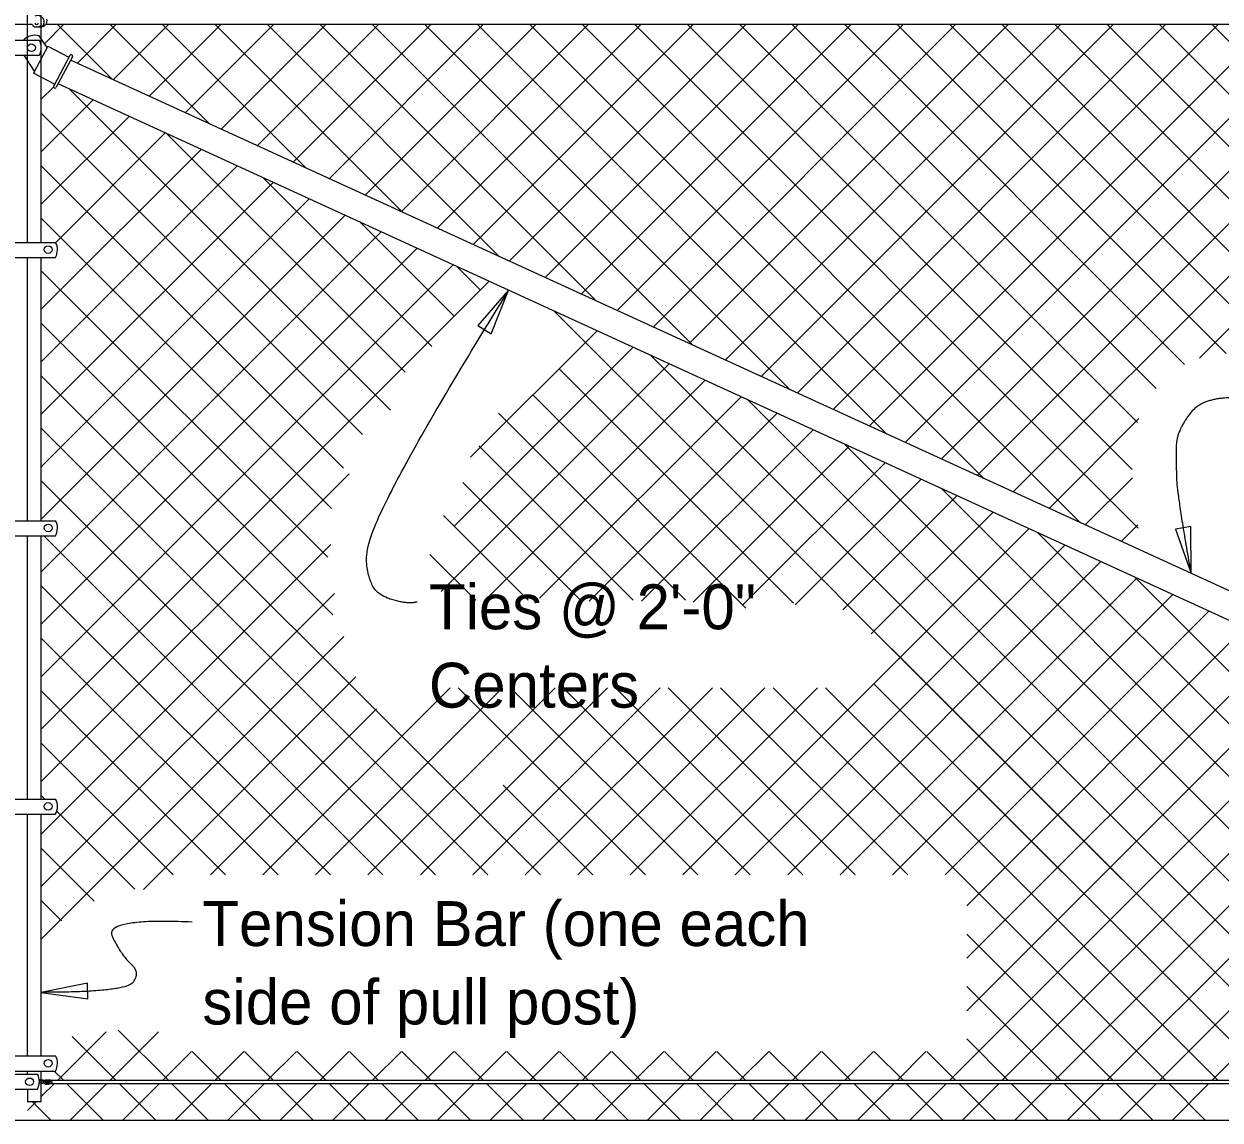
# Model space of a CAD drawing. Extents: x 0 to 41.2, y 0 to 26.
# Drawn here: x 12.4 to 17.77, y 17.47 to 22.39 of the extents above; entities that cross this region are included whole.
import ezdxf

# ---------------------------------------------------------------- set-up
doc = ezdxf.new("R2010")
doc.units = 0
for name, color, linetype in [('Dimension', 7, 'Continuous'), ('Miscellaneous', 7, 'Continuous'), ('SteelMisc', 7, 'Continuous'), ('SupstrConc', 7, 'Continuous'), ('TextStructures', 7, 'Continuous')]:
    doc.layers.add(name, color=color, linetype=linetype)

msp = doc.modelspace()

# ---------------------------------------------------------------- linework, layer by layer
at = {"layer": 'Dimension'}
for points in [[(14.5761, 21.1957), (14.4371, 21.0368), (14.4972, 20.9998)], [(17.6408, 19.9239), (17.6405, 20.1351), (17.5709, 20.1232)], [(12.4771, 18.0429), (12.6863, 18.0139), (12.6842, 18.0844)]]:
    msp.add_lwpolyline(points, close=True, dxfattribs=at)
for points in [[(14.1644, 19.7962), (14.1177, 19.782), (13.9347, 19.8493), (13.9433, 20.1759), (14.5761, 21.1958)], [(17.8509, 20.7118), (17.6943, 20.72), (17.5763, 20.5615), (17.5733, 20.4403), (17.578, 20.2726), (17.6407, 19.9238)], [(13.1545, 18.3586), (12.7557, 18.3765), (12.8361, 18.2097), (12.9224, 18.1322), (12.8539, 18.0428), (12.4771, 18.0428)]]:
    msp.add_open_spline(points, degree=2, dxfattribs=at)
at = {"layer": 'Miscellaneous'}
for p, q in [((12.4911, 22.303), (12.5782, 22.39)), ((12.5487, 22.39), (12.7955, 22.1432)), ((12.6389, 22.215), (12.8139, 22.39)), ((12.7844, 22.39), (13.2304, 21.944)), ((12.8005, 22.1409), (13.0496, 22.39)), ((12.9622, 22.0669), (13.2853, 22.39)), ((13.0201, 22.39), (13.6653, 21.7448)), ((13.1238, 21.9928), (13.521, 22.39)), ((13.2558, 22.39), (14.1002, 21.5456)), ((13.2855, 21.9188), (13.7567, 22.39)), ((13.4471, 21.8448), (13.9924, 22.39)), ((13.4916, 22.39), (14.5351, 21.3464)), ((13.6088, 21.7707), (14.2281, 22.39)), ((13.7273, 22.39), (14.9701, 21.1472)), ((13.7705, 21.6967), (14.4638, 22.39)), ((13.9321, 21.6226), (14.6995, 22.39)), ((13.963, 22.39), (15.405, 20.948)), ((14.0938, 21.5486), (14.9352, 22.39)), ((14.1987, 22.39), (15.8399, 20.7488)), ((14.2554, 21.4745), (15.1709, 22.39)), ((14.4171, 21.4005), (15.4066, 22.39)), ((14.4344, 22.39), (16.2748, 20.5496)), ((14.5787, 21.3264), (15.6423, 22.39)), ((14.6701, 22.39), (16.7097, 20.3504)), ((14.7404, 21.2524), (15.878, 22.39)), ((14.9021, 21.1784), (16.1137, 22.39)), ((14.9058, 22.39), (17.1446, 20.1512)), ((15.0637, 21.1043), (16.3494, 22.39)), ((15.1415, 22.39), (17.4036, 20.1279)), ((15.2254, 21.0303), (16.5851, 22.39)), ((15.3772, 22.39), (17.3758, 20.3914)), ((15.387, 20.9562), (16.8208, 22.39)), ((15.5487, 20.8822), (17.0565, 22.39)), ((15.6129, 22.39), (16.224, 21.7789)), ((15.7103, 20.8081), (17.2922, 22.39)), ((15.8486, 22.39), (16.224, 22.0146)), ((15.872, 20.7341), (17.5279, 22.39)), ((16.0337, 20.66), (17.7636, 22.39)), ((16.0843, 22.39), (17.6113, 20.8629)), ((16.1953, 20.586), (17.9993, 22.39)), ((16.32, 22.39), (17.7983, 20.9117)), ((16.357, 20.5119), (18.235, 22.39)), ((16.5186, 20.4379), (18.4707, 22.39)), ((16.5557, 22.39), (17.9778, 20.9679)), ((16.6803, 20.3639), (18.7064, 22.39)), ((16.7914, 22.39), (18.2135, 20.9679)), ((16.8419, 20.2898), (18.9421, 22.39)), ((17.0271, 22.39), (18.4492, 20.9679)), ((17.2628, 22.39), (18.6849, 20.9679)), ((17.4985, 22.39), (18.9206, 20.9679)), ((17.679, 20.8912), (19.1778, 22.39)), ((17.7342, 22.39), (19.1563, 20.9679)), ((12.4771, 22.0532), (12.532, 22.1081)), ((12.6041, 22.099), (14.0454, 20.6576)), ((12.4771, 21.8175), (12.71, 22.0505)), ((15.95, 22.0528), (17.4005, 20.6024)), ((16.1857, 22.0528), (17.4843, 20.7543)), ((12.4771, 21.9903), (13.9198, 20.5475)), ((12.4771, 21.5818), (12.8717, 21.9764)), ((12.5416, 21.4106), (13.0333, 21.9024)), ((13.0389, 21.8998), (14.1107, 20.8281)), ((12.4771, 21.1104), (13.195, 21.8283)), ((12.4771, 21.7546), (13.8345, 20.3972)), ((12.4771, 20.8747), (13.3567, 21.7543)), ((12.4771, 20.639), (13.5183, 21.6802)), ((13.4738, 21.7006), (14.2316, 20.9428)), ((12.4771, 20.4033), (13.68, 21.6062)), ((14.5173, 21.6), (14.649, 21.4683)), ((12.4771, 20.1676), (13.8416, 21.5322)), ((12.4771, 21.5189), (13.78, 20.2159)), ((13.9087, 21.5014), (14.3312, 21.0789)), ((12.4771, 19.9319), (14.0033, 21.4581)), ((12.4771, 19.6962), (14.165, 21.3841)), ((12.4771, 19.4605), (14.3266, 21.31)), ((12.4771, 21.2832), (13.7633, 19.997)), ((14.3436, 21.3022), (14.4491, 21.1968)), ((12.4771, 19.2248), (14.4883, 21.236)), ((14.7785, 21.103), (17.3305, 18.5511)), ((12.4771, 21.0475), (13.7861, 19.7384)), ((14.4052, 20.4458), (14.9733, 21.0138)), ((14.3305, 20.1354), (15.1349, 20.9398)), ((15.2134, 20.9039), (18.4687, 17.6486)), ((14.2734, 19.8426), (15.2966, 20.8658)), ((12.4771, 20.8118), (14.7187, 18.5701)), ((14.4778, 19.8113), (15.4582, 20.7917)), ((14.8026, 20.8432), (15.8555, 19.7904)), ((14.6848, 20.7254), (15.6418, 19.7684)), ((14.7149, 19.8127), (15.6199, 20.7177)), ((15.6483, 20.7047), (18.7044, 17.6486)), ((14.53, 20.6445), (15.3708, 19.8037)), ((14.9378, 19.7999), (15.7815, 20.6436)), ((17.0036, 20.2158), (17.4071, 20.6192)), ((12.4771, 20.5761), (14.483, 18.5701)), ((15.1731, 19.7995), (15.9432, 20.5696)), ((14.4418, 20.497), (15.1351, 19.8037)), ((15.4049, 19.7956), (16.1049, 20.4955)), ((16.0832, 20.5055), (18.9401, 17.6486)), ((15.6276, 19.7826), (16.2665, 20.4215)), ((12.4771, 18.9891), (13.8596, 20.3716)), ((12.4771, 20.3404), (14.2473, 18.5701)), ((14.3708, 20.3323), (14.8994, 19.8037)), ((15.8633, 19.7826), (16.4282, 20.3475)), ((17.1653, 20.1417), (17.3773, 20.3538)), ((16.0774, 19.761), (16.5898, 20.2734)), ((16.5181, 20.3063), (19.1758, 17.6486)), ((14.283, 20.1844), (14.6637, 19.8037)), ((16.2045, 19.6524), (16.7515, 20.1994)), ((12.4884, 20.0933), (14.0116, 18.5701)), ((16.1384, 19.3505), (16.9132, 20.1253)), ((16.953, 20.1071), (19.4115, 17.6486)), ((17.3269, 20.0677), (17.4014, 20.1422)), ((12.4771, 18.7534), (13.778, 20.0543)), ((15.5936, 18.5701), (17.0748, 20.0513)), ((14.2226, 20.0091), (14.428, 19.8037)), ((15.8293, 18.5701), (17.2365, 19.9772)), ((16.065, 18.5701), (17.3981, 19.9032)), ((17.3879, 19.9079), (19.6472, 17.6486)), ((12.4771, 19.869), (13.7759, 18.5701)), ((12.4771, 18.5177), (13.7936, 19.8342)), ((16.3007, 18.5701), (17.5598, 19.8292)), ((16.5364, 18.5701), (17.7215, 19.7551)), ((16.6339, 18.4318), (17.8831, 19.6811)), ((12.4771, 18.282), (13.8357, 19.6406)), ((12.4771, 19.6333), (13.5402, 18.5701)), ((16.2952, 19.5864), (18.233, 17.6486)), ((16.6339, 18.1961), (18.0448, 19.607)), ((16.6339, 17.9604), (18.2064, 19.533)), ((12.9361, 18.5053), (13.8901, 19.4593)), ((16.5577, 17.6486), (18.3681, 19.4589)), ((12.4771, 19.3976), (13.3045, 18.5701)), ((13.4723, 18.5701), (14.3131, 19.4109)), ((13.708, 18.5701), (14.5488, 19.4109)), ((13.9437, 18.5701), (14.7845, 19.4109)), ((14.1794, 18.5701), (15.0202, 19.4109)), ((14.3493, 19.4109), (15.1901, 18.5701)), ((14.4151, 18.5701), (15.2559, 19.4109)), ((14.585, 19.4109), (15.4258, 18.5701)), ((14.6508, 18.5701), (15.4916, 19.4109)), ((14.8207, 19.4109), (15.6615, 18.5701)), ((14.8865, 18.5701), (15.7274, 19.4109)), ((15.0564, 19.4109), (15.8972, 18.5701)), ((15.1222, 18.5701), (15.9631, 19.4109)), ((15.2921, 19.4109), (16.1329, 18.5701)), ((15.3579, 18.5701), (16.1988, 19.4109)), ((15.5278, 19.4109), (16.3686, 18.5701)), ((15.7635, 19.4109), (17.5259, 17.6486)), ((15.9992, 19.4109), (17.7616, 17.6486)), ((16.0143, 19.3958), (16.8591, 18.5511)), ((16.2168, 19.429), (17.0948, 18.5511)), ((16.2349, 19.4109), (17.9973, 17.6486)), ((16.7934, 17.6486), (18.5298, 19.3849)), ((13.2366, 18.5701), (13.9832, 19.3167)), ((17.0291, 17.6486), (18.6914, 19.3109)), ((17.2648, 17.6486), (18.8531, 19.2368)), ((12.4771, 19.1619), (13.0688, 18.5701)), ((17.5005, 17.6486), (19.0147, 19.1628)), ((17.7362, 17.6486), (19.1764, 19.0887)), ((14.5513, 18.9732), (14.9544, 18.5701)), ((12.4771, 18.9262), (12.4923, 18.9109)), ((12.5465, 18.8568), (12.897, 18.5062)), ((12.4771, 18.6905), (12.715, 18.4525)), ((12.4771, 18.4548), (12.5674, 18.3644)), ((16.6339, 18.3049), (17.2902, 17.6486)), ((16.6339, 18.0692), (17.0545, 17.6486)), ((12.5508, 17.6486), (12.7683, 17.8661)), ((12.6161, 17.8443), (12.8118, 17.6486)), ((12.7865, 17.6486), (13.0028, 17.8649)), ((12.8223, 17.8738), (13.0476, 17.6486)), ((16.6339, 17.8335), (16.8188, 17.6486)), ((13.0222, 17.6486), (13.1513, 17.7777)), ((13.1541, 17.7777), (13.2833, 17.6486)), ((13.2579, 17.6486), (13.387, 17.7777)), ((13.3898, 17.7777), (13.519, 17.6486)), ((13.4936, 17.6486), (13.6227, 17.7777)), ((13.6255, 17.7777), (13.7547, 17.6486)), ((13.7293, 17.6486), (13.8584, 17.7777)), ((13.8612, 17.7777), (13.9904, 17.6486)), ((13.965, 17.6486), (14.0941, 17.7777)), ((14.0969, 17.7777), (14.2261, 17.6486)), ((14.2007, 17.6486), (14.3298, 17.7777)), ((14.3326, 17.7777), (14.4618, 17.6486)), ((14.4364, 17.6486), (14.5655, 17.7777)), ((14.5683, 17.7777), (14.6975, 17.6486)), ((14.6721, 17.6486), (14.8012, 17.7777)), ((14.804, 17.7777), (14.9332, 17.6486)), ((14.9078, 17.6486), (15.0369, 17.7777)), ((15.0397, 17.7777), (15.1689, 17.6486)), ((15.1435, 17.6486), (15.2726, 17.7777)), ((15.2754, 17.7777), (15.4046, 17.6486)), ((15.3792, 17.6486), (15.5083, 17.7777)), ((15.5111, 17.7777), (15.6403, 17.6486)), ((15.6149, 17.6486), (15.744, 17.7777)), ((15.7468, 17.7777), (15.876, 17.6486)), ((15.8506, 17.6486), (15.9797, 17.7777)), ((15.9825, 17.7777), (16.1117, 17.6486)), ((16.0863, 17.6486), (16.2155, 17.7777)), ((16.2182, 17.7777), (16.3474, 17.6486)), ((16.322, 17.6486), (16.4503, 17.7768)), ((16.4539, 17.7777), (16.5831, 17.6486)), ((12.5351, 17.6896), (12.5761, 17.6486)), ((12.4771, 17.5748), (12.536, 17.6338)), ((12.5909, 17.6338), (12.7554, 17.4693)), ((12.6072, 17.4693), (12.7717, 17.6338)), ((12.8266, 17.6338), (12.9911, 17.4693)), ((12.8429, 17.4693), (13.0074, 17.6338)), ((13.0623, 17.6338), (13.2268, 17.4693)), ((13.0786, 17.4693), (13.2431, 17.6338)), ((13.298, 17.6338), (13.4625, 17.4693)), ((13.3143, 17.4693), (13.4788, 17.6338)), ((13.5337, 17.6338), (13.6982, 17.4693)), ((13.5501, 17.4693), (13.7145, 17.6338)), ((13.7694, 17.6338), (13.9339, 17.4693)), ((13.7858, 17.4693), (13.9502, 17.6338)), ((14.0051, 17.6338), (14.1696, 17.4693)), ((14.0215, 17.4693), (14.1859, 17.6338)), ((14.2408, 17.6338), (14.4053, 17.4693)), ((14.2572, 17.4693), (14.4216, 17.6338)), ((14.4765, 17.6338), (14.641, 17.4693)), ((14.4929, 17.4693), (14.6573, 17.6338)), ((14.7122, 17.6338), (14.8767, 17.4693)), ((14.7286, 17.4693), (14.893, 17.6338)), ((14.9479, 17.6338), (15.1124, 17.4693)), ((14.9643, 17.4693), (15.1287, 17.6338)), ((15.1836, 17.6338), (15.3481, 17.4693)), ((15.2, 17.4693), (15.3644, 17.6338)), ((15.4193, 17.6338), (15.5838, 17.4693)), ((15.4357, 17.4693), (15.6001, 17.6338)), ((15.655, 17.6338), (15.8195, 17.4693)), ((15.6714, 17.4693), (15.8359, 17.6338)), ((15.8907, 17.6338), (16.0552, 17.4693)), ((15.9071, 17.4693), (16.0716, 17.6338)), ((16.1264, 17.6338), (16.2909, 17.4693)), ((16.1428, 17.4693), (16.3073, 17.6338)), ((16.3621, 17.6338), (16.5266, 17.4693)), ((16.3785, 17.4693), (16.543, 17.6338)), ((16.5978, 17.6338), (16.7623, 17.4693)), ((16.6142, 17.4693), (16.7787, 17.6338)), ((16.8335, 17.6338), (16.998, 17.4693)), ((16.8499, 17.4693), (17.0144, 17.6338)), ((17.0692, 17.6338), (17.2337, 17.4693)), ((17.0856, 17.4693), (17.2501, 17.6338)), ((17.3049, 17.6338), (17.4694, 17.4693)), ((17.3213, 17.4693), (17.4858, 17.6338)), ((17.5406, 17.6338), (17.7051, 17.4693)), ((17.557, 17.4693), (17.7215, 17.6338)), ((12.4146, 17.5123), (12.455, 17.5528)), ((12.4362, 17.5528), (12.5197, 17.4693))]:
    msp.add_line(p, q, dxfattribs=at)
at = {"layer": 'SteelMisc'}
for p, q in [((12.4146, 21.4109), (12.4146, 22.5933)), ((12.4771, 21.4109), (12.4771, 22.5933)), ((12.352, 22.39), (12.4351, 22.39)), ((12.4978, 22.39), (21.9118, 22.39)), ((11.9439, 22.3192), (12.4686, 22.3192)), ((12.5028, 22.2852), (12.468, 22.3383)), ((11.9439, 22.2514), (12.4686, 22.2514)), ((12.4467, 22.1792), (12.3998, 22.2509)), ((12.5062, 22.2918), (12.4425, 22.1712)), ((12.5062, 22.2918), (12.6005, 22.2419)), ((12.6051, 22.2506), (12.5327, 22.1134)), ((12.617, 22.2443), (12.5445, 22.1072)), ((21.8588, 17.9919), (12.6088, 22.2288)), ((12.5368, 22.1214), (12.4425, 22.1712)), ((21.8028, 17.8858), (12.5526, 22.1225)), ((12.0505, 21.4109), (12.5416, 21.4109)), ((12.0505, 21.3433), (12.5408, 21.3433)), ((12.4146, 20.1609), (12.4146, 21.3433)), ((12.4771, 20.1609), (12.4771, 21.3433)), ((12.0505, 20.1609), (12.5416, 20.1609)), ((12.0505, 20.0933), (12.5408, 20.0933)), ((12.4146, 18.9109), (12.4146, 20.0933)), ((12.4771, 18.9109), (12.4771, 20.0933)), ((12.0505, 18.9109), (12.5416, 18.9109)), ((12.0505, 18.8433), (12.5408, 18.8433)), ((12.4146, 17.7573), (12.4146, 18.8433)), ((12.4771, 17.7573), (12.4771, 18.8433)), ((12.0505, 17.7573), (12.5416, 17.7573)), ((11.9524, 17.6757), (12.4602, 17.6757)), ((12.0505, 17.6896), (12.5408, 17.6896)), ((12.4146, 17.6757), (12.4146, 17.6896)), ((12.4771, 17.6518), (12.4771, 17.6896)), ((12.4676, 17.6532), (12.4941, 17.6488)), ((12.4681, 17.6481), (12.4941, 17.644)), ((12.4681, 17.6328), (12.5018, 17.6385)), ((12.4685, 17.6375), (12.4986, 17.6425)), ((12.4771, 17.6389), (12.4771, 17.6467)), ((12.4771, 17.5528), (12.4771, 17.6343)), ((12.5141, 17.6338), (21.9119, 17.6338)), ((12.5154, 17.6486), (21.8852, 17.6486)), ((11.9526, 17.6079), (12.4599, 17.6079)), ((12.4146, 17.6079), (12.4146, 17.5528)), ((12.4146, 17.5528), (12.4771, 17.5528))]:
    msp.add_line(p, q, dxfattribs=at)
for centre, start, end in [((12.6109, 22.2474), 332.149, 152.149), ((12.5384, 22.1102), 152.149, 332.149)]:
    msp.add_arc(centre, 0.00673, start, end, dxfattribs=at)
for centre, major_axis, ratio, start_param, end_param in [((12.4603, 22.4014), (-0.0295, 0), 0.957868, 2.287002, 5.15055), ((12.4779, 22.4042), (0.0249, 0), 0.957868, 5.476514, 6.65252), ((12.4572, 22.4013), (-0.0251, 0), 0.957868, 0.487549, 0.751829), ((12.4643, 22.4133), (-0.0391, 0), 0.957868, 0.863445, 1.149078), ((12.4558, 22.3967), (0.00795, 0), 0.957868, 3.283494, 6.243757), ((12.4569, 22.3945), (-0.0206, -0.0021), 0.798607, 1.063032, 2.96375), ((12.4704, 22.3945), (-0.0206, -0.0021), 0.798607, 1.113032, 1.956656), ((12.4765, 22.4002), (-0.0231, 0), 0.957868, 1.44404, 2.503632), ((12.4514, 22.27), (-0.0647, 0.0342), 0.957868, 4.95193, 6.011789), ((12.3994, 22.2851), (0.0776, 0), 0.957868, 5.810211, 6.75616), ((12.472, 21.3778), (0.0776, 0), 0.957868, 5.801046, 6.744962), ((12.472, 20.1278), (0.0776, 0), 0.957868, 5.800848, 6.744767), ((12.472, 18.8777), (0.0776, 0), 0.957868, 5.810211, 6.745158), ((12.472, 17.7241), (0.0776, 0), 0.957868, 5.800651, 6.745353), ((12.3909, 17.6421), (0.0776, 0), 0.957868, 5.803915, 6.752041), ((12.4993, 17.6387), (-0.0095, 0), 0.957868, 5.623869, 6.017994), ((12.4993, 17.6387), (-0.0095, 0), 0.957868, 0.252467, 1.247174), ((12.4953, 17.6395), (0.0115, -0.0041), 0.737732, 5.048267, 8.212701), ((12.4934, 17.6346), (0.00982, 0), 0.957868, 0.636815, 1.505671), ((12.4988, 17.637), (0.00301, 0), 0.957868, 2.989083, 5.497792), ((12.4994, 17.6392), (-0.00453, 0), 0.957868, 5.149727, 5.551998), ((12.501, 17.6403), (-0.00872, 0), 0.957868, 2.114937, 5.0803), ((12.4966, 17.6379), (0.00527, 0), 0.957868, 5.660961, 6.743457), ((12.4988, 17.637), (0.00301, 0), 0.957868, 6.243757, 6.781286), ((12.5071, 17.6399), (0.00944, 0), 0.957868, 4.319295, 6.652508), ((12.5076, 17.6408), (-0.00872, 0), 0.957868, 3.422117, 5.180096), ((12.5076, 17.6408), (-0.00503, 0), 0.92697, 1.789502, 4.651061), ((12.5123, 17.6353), (-0.0142, 0), 0.957868, 3.175145, 4.85532), ((12.5043, 17.6203), (0.0274, 0), 0.957868, 0.63108, 1.149654)]:
    msp.add_ellipse(centre, major_axis=major_axis, ratio=ratio, start_param=start_param, end_param=end_param, dxfattribs=at)
for centre, major_axis in [((12.4327, 22.2847), (-0.0178, 0)), ((12.5079, 21.3782), (-0.0177, 0)), ((12.5079, 20.1282), (-0.0177, 0)), ((12.5079, 18.8781), (-0.0177, 0)), ((12.5079, 17.7245), (-0.0177, 0)), ((12.4242, 17.6412), (-0.0178, 0))]:
    msp.add_ellipse(centre, major_axis=major_axis, ratio=0.957868, dxfattribs=at)
at = {"layer": 'SupstrConc'}
msp.add_line((12.3521, 17.4693), (18.8204, 17.4693), dxfattribs=at)

# ---------------------------------------------------------------- texts
at = {"layer": 'TextStructures'}
for s, p in [('Ties @ 2\'-0" ', (14.2179, 19.6734)), ('Centers', (14.2179, 19.3214)), ('Tension Bar (one each ', (13.2005, 18.2509)), ('side of pull post)', (13.2005, 17.8989))]:
    msp.add_text(s, height=0.2016, dxfattribs=at).set_placement(p)

doc.saveas('drawing.dxf')
